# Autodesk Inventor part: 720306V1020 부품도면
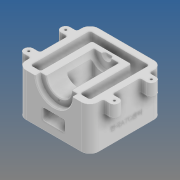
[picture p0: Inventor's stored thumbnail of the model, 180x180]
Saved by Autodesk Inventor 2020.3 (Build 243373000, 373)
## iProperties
Created: 2022-03
Part Number: 720306V1020 부품도면
Material: 일반
Document SubType Name: Modeling
Designer: EZDESIGN
Density: 1 g/cm^3
Appearance: 기본값
Mass: 379.412 g
Surface Area: 845.188 cm^2
Volume: 379.412 cm^3
Author: EZDESIGN
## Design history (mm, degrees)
sketch "스케치1"
  geometry: L1 (55, 55)-(-55, 55); L2 (-55, 55)-(-55, -55); L3 (-55, -55)-(55, -55); L4 (55, -55)-(55, 55); L5 (55, 55)-(-55, -55); L6 (-55, 55)-(55, -55); L7 (45, 45)-(45, -45); L8 (45, -45)-(-45, -45); L9 (-45, -45)-(-45, 45); L10 (-45, 45)-(-30, 45); L11 (-30, 45)-(-30, -33); L12 (-30, -33)-(30, -33); L13 (30, -33)-(30, 45); L14 (30, 45)-(45, 45); 1 further point
  constraints: 28 end point, 7 perpendicular, 2 midpoint, 2 parallel, 2 point on line, 1 horizontal, 1 vertical
  dimensions: "d0" = 110 distance of L3.end L2.end; "d1" = 110 distance of L2.end L1.end; "d2" = 10 distance between parallel lines of L2 L9; "d3" = 25 distance from line of L2 L11.end; "d4" = 60 distance of L11.end L12.end; "d7" = 10 distance between parallel lines of L1 L14; "d8" = 10 distance between parallel lines of L4 L7; "d10" = 10 distance between parallel lines of L8 L3; "d11" = 22 distance between parallel lines of L3 L12
extrude "돌출1" new body sketch "스케치1" distance "d12" = 65; taper "d13" = 0 deg
sketch "스케치2"
  geometry: L1 (55, -55)-(55, 55) reference; L2 (55, 55)-(-55, 55) reference; L3 (-55, 55)-(-55, -55) reference; L4 (-55, -55)-(55, -55) reference; L5 (-45, -45)-(-45, 45) reference; L6 (-45, 45)-(45, 45) reference; L7 (45, 45)-(45, -45) reference; L8 (45, -45)-(30, -45) reference; L9 (30, -45)-(30, 33) reference; L10 (30, 33)-(-30, 33) reference; L11 (-30, 33)-(-30, -45) reference; L12 (-30, -45)-(-45, -45) reference; L13 (-55, 55)-(-55, -55) reference; L14 (55, -55)-(55, 55) reference; L15 (-65, 35)-(-55, 35); L16 (-65, 21)-(-55, 21); L17 (65, 35)-(55, 35); L18 (65, 21)-(55, 21); L19 (-107.819, 0)-(107.819, 0); L20 (-65, -35)-(-55, -35); L21 (-65, -21)-(-55, -21); L22 (65, -21)-(55, -21); L23 (65, -35)-(55, -35); A1 r 7 centre (-65, 28) between (-65, 35) and (-65, 21); A2 r 7 centre (65, 28) between (65, 35) and (65, 21); A3 r 7 centre (-65, -28) between (-65, -35) and (-65, -21); A4 r 7 centre (65, -28) between (65, -35) and (65, -21); 10 further points
  constraints: 18 end point, 10 symmetric about line, 8 point on circle, 5 horizontal, 4 centre point, 4 point on line, 4 tangent, 1 coincident, 1 horizontal alignment, 1 midpoint, 2 other
  dimensions: "d14" = 14 diameter of A1; "d15" = 14 diameter of A2; "d18" = 65 horizontal distance of point (0, 0) A1.centre; "d19" = 130 distance of A2.centre A1.centre; "d20" = 27 distance from line of A1.centre L2; "d21" = 215.63792 distance of L19.start L19.end
extrude "돌출2" join sketch "스케치2" distance "d22" = 20; taper "d23" = 0 deg
sketch "스케치3"
  geometry: L1 (0, 0)-(110, 0) reference; L2 (0, 0)-(0, -65) reference; L3 (110, -65)-(0, -65) reference; L4 (110, 0)-(110, -65) reference; C1 r 28 at (55, 0); 3 further points
  constraints: 1 centre point, 1 coincident
  dimensions: "d24" = 56 diameter of C1
extrude "돌출3" cut sketch "스케치3" distance "d26" = 8; taper "d27" = 0 deg
sketch "스케치4"
  geometry: C1 r 19 at (55, 0); 1 further point
  constraints: 1 centre point, 1 coincident
  dimensions: "d28" = 38 diameter of C1
extrude "돌출4" cut sketch "스케치4" distance "d29" = 72; taper "d30" = 0 deg
sketch "스케치5" dims "d7" = 10
  geometry: L1 (0, 68.674)-(0, -68.674); L2 (0, -21)-(-20, -21) reference; L3 (-20, -21)-(-20, -35) reference; L4 (-20, -35)-(0, -35) reference; L5 (0, -55)-(0, -35) reference; L6 (0, -55)-(-65, -55) reference; L7 (-65, 55)-(-65, -55) reference; L8 (0, 55)-(-65, 55) reference; L9 (0, 35)-(0, 55) reference; L10 (0, 35)-(-20, 35) reference; L11 (-20, 35)-(-20, 21) reference; L12 (-20, 21)-(0, 21) reference; L13 (0, -21)-(0, 21) reference; L14 (0, -33)-(0, 45) reference; L15 (0, -33)-(-65, -33) reference; L16 (-65, 45)-(-65, -33) reference; L17 (0, 45)-(-65, 45) reference; L18 (0, -29)-(-4.613, -29); L19 (-5.479, -28.5)-(-7.5, -25); L20 (-19, -25)-(0, -25) reference; A1 r 1 centre (-4.613, -28) between (-5.479, -28.5) and (-4.613, -29); 2 further points
  constraints: 6 end point, 2 point on circle, 2 point on line, 2 tangent, 1 centre point, 1 coincident, 1 horizontal, 1 midpoint, 1 vertical, 1 vertical alignment
  dimensions: "d31" = 4 distance of L20.end L18.start; "d32" = 15 diameter of L19.end L1; "d33" = 30 deg angle of L1 L19; "d34" = 1 radius of A1; "d35" = 137.34853 distance of L1.start L1.end
revolve "회전1" sketch "스케치5" stored, may be unused: angle "d36" = 90 deg
fillet "모깎기1" dims "d37" = 1
sketch "스케치8"
  geometry: L1 (-35, -33)-(-55.304, 42.776); L2 (-58.202, 45)-(-65, 45); L3 (0, -33)-(-65, -33) reference; L4 (0, -33)-(0, 45) reference; L5 (0, -33)-(-65, -33) reference; L6 (-65, 45)-(-65, -33) reference; L7 (0, 45)-(-65, 45) reference; L8 (0, 55)-(-65, 55) reference; L9 (-65, 55)-(-65, -55) reference; A1 r 3 centre (-58.202, 42) between (-55.304, 42.776) and (-58.202, 45); 3 further points
  constraints: 4 end point, 4 point on line, 2 point on circle, 2 tangent, 1 centre point, 1 horizontal
  dimensions: "d52" = 10 distance between parallel lines of L8 L2; "d53" = 75 deg angle of L3 L1; "d54" = 30 distance from line of L9 L1.start; "d82" = 3 radius of A1 (derived)
extrude "돌출6" cut sketch "스케치8" stored distance "d55" = 60; taper "d56" = 0 deg
sketch "스케치6"
  geometry: L1 (-26.157, 19)-(-9.157, 19); L2 (-9.157, 19)-(-9.157, -19); L3 (-9.157, -19)-(-33.575, -19); L4 (-33.575, -19)-(-53.403, 55); L5 (-26.157, 19)-(-35.803, 55); L6 (-19, 47)-(-19, -24) reference; L7 (0, 35)-(-20, 35) reference; L8 (0, -33)-(0, 45) reference; L9 (0, -33)-(-35, -33) reference; L10 (0, 45)-(-58.202, 45) reference; L11 (0, -21)-(-20, -21) reference; L12 (-20, -21)-(-20, -35) reference; L13 (-20, -35)-(0, -35) reference; L14 (0, -55)-(0, -35) reference; L15 (0, -55)-(-65, -55) reference; L16 (-65, 55)-(-65, -55) reference; L17 (0, 55)-(-65, 55) reference; L18 (0, 35)-(0, 55) reference; L19 (0, 35)-(-20, 35) reference; L20 (-20, 35)-(-20, 21) reference; L21 (-20, 21)-(0, 21) reference; L22 (0, -21)-(0, 21) reference; L23 (-19, 47)-(0, 47) reference; L24 (0, 55)-(0, 55) reference; L25 (0, 47)-(0, 55) reference; L26 (0, 47)-(0, 47) reference; L27 (0, 55)-(0, 47) reference; L28 (-20, -35)-(0, -35) reference; L29 (0, -45)-(-65, -45) reference; L30 (0, 45)-(0, -45) reference; L31 (0, 45)-(-65, 45) reference; L32 (-65, -45)-(-65, 45) reference; L33 (0, -45)-(-65, -45) reference; L34 (-35, -33)-(-55.304, 42.776) reference; L35 (-35, -33)-(-55.9, 45) reference; L36 (0, 45)-(-65, 45) reference; A1 r 3 centre (-58.202, 42) between (-55.304, 42.776) and (-58.202, 45) reference; 1 further point
  constraints: 10 end point, 2 perpendicular, 2 point on line, 1 horizontal, 1 parallel
  dimensions: "d38" = 38 distance of L1.end L2.end; "d42" = 17 distance between parallel lines of L4 L5; "d45" = 36 distance from line of L17 L1.end; "d57" = 5 distance between parallel lines of L34 L4; "d58" = 17 distance of L1.start L1.end
  node "투영된 루프5"
  node "투영된 루프6"
  node "투영된 루프7"
  node "투영된 루프8"
extrude "돌출5" cut sketch "스케치6" stored distance "d47" = 34; taper "d48" = 0 deg
sketch "스케치9" dims "d59" = 46
  geometry: 3 further points
  constraints: 2 vertical alignment, 1 coincident, 2 other
sketch "스케치10" dims "d74" = 46
  geometry: 3 further points
  constraints: 2 vertical alignment, 1 coincident, 2 other
hole "구멍1" sketch "스케치10" at (55, -23) diameter "d60" = 3.242; stored, may be unused: countersink angle "d64" = 82 deg, drill point angle "d66" = 118 deg; dims "d61" = 9, "d62" = 11, "d63" = 2.6, "d65" = 11
sketch "스케치11"
  geometry: L1 (-45, -45)-(-45, 45) reference; L2 (-45, 45)-(45, 45) reference; L3 (45, 45)-(45, -45) reference; L4 (45, -45)-(30, -45) reference; L5 (30, -45)-(30, 33) reference; L6 (30, 33)-(-30, 33) reference; L7 (-30, 33)-(-30, -45) reference; L8 (-30, -45)-(-45, -45) reference; L9 (-7.5, 25)-(-5.479, 28.5) reference; L10 (-4.613, 29)-(4.613, 29) reference; L11 (5.479, 28.5)-(7.5, 25) reference; L12 (7.5, 25)-(18, 25) reference; L13 (19, 24)-(19, -47) reference; L14 (19, -47)-(28, -47) reference; L15 (28, -47)-(28, -55) reference; L16 (28, -55)-(55, -55) reference; L17 (55, -55)-(55, -35) reference; L18 (55, -35)-(65, -35) reference; L19 (65, -21)-(55, -21) reference; L20 (55, -21)-(55, 21) reference; L21 (55, 21)-(65, 21) reference; L22 (65, 35)-(55, 35) reference; L23 (55, 35)-(55, 55) reference; L24 (55, 55)-(-55, 55) reference; L25 (-55, 55)-(-55, 35) reference; L26 (-55, 35)-(-65, 35) reference; L27 (-65, 21)-(-55, 21) reference; L28 (-55, 21)-(-55, -21) reference; L29 (-55, -21)-(-65, -21) reference; L30 (-65, -35)-(-55, -35) reference; L31 (-55, -35)-(-55, -55) reference; L32 (-55, -55)-(-28, -55) reference; L33 (-28, -55)-(-28, -47) reference; L34 (-28, -47)-(-19, -47) reference; L35 (-19, -47)-(-19, 24) reference; L36 (-18, 25)-(-7.5, 25) reference; A1 r 1 centre (-4.613, 28) between (-4.613, 29) and (-5.479, 28.5) reference; A2 r 1 centre (4.613, 28) between (5.479, 28.5) and (4.613, 29) reference; A3 r 1 centre (18, 24) between (19, 24) and (18, 25) reference; A4 r 7 centre (65, -28) between (65, -35) and (65, -21) reference; A5 r 7 centre (65, 28) between (65, 21) and (65, 35) reference; A6 r 7 centre (-65, 28) between (-65, 35) and (-65, 21) reference; A7 r 7 centre (-65, -28) between (-65, -21) and (-65, -35) reference; A8 r 1 centre (-18, 24) between (-18, 25) and (-19, 24) reference; 5 further points
  constraints: 4 coincident
hole "구멍2" sketch "스케치11" at (-65, 28), (-65, -28), (65, -28), (65, 28) diameter "d67" = 3.242; stored, may be unused: countersink angle "d71" = 82 deg, drill point angle "d73" = 118 deg; dims "d68" = 9, "d69" = 11, "d70" = 2.6, "d72" = 11
sketch "스케치12"
  geometry: L1 (110, 0)-(0, 0) reference; L2 (0, 65)-(0, 0) reference; 2 further points
  constraints: 1 other
  dimensions: "d75" = 20 distance from line of L1 point (55, 20); "d76" = 55 distance from line of L2 point (55, 20)
feature "엠보싱1" sketch "스케치12" dims "d0" = 110, "d1" = 110, "d2" = 10, "d3" = 25, "d4" = 60, "d7" = 10, "d8" = 10, "d10" = 10, "d11" = 22, "d77" = 0.5, "d78" = 0
fillet "모깎기2" dims "d79" = 3
fillet "모깎기3" dims "d80" = 3
fillet "모깎기4" dims "d81" = 3
fillet "모깎기5" dims "d83" = 3
fillet "모깎기6" dims "d84" = 3
fillet "모깎기7" dims "d85" = 3
chamfer "모따기1" distance "d86" = 1; stored, may be unused: second distance "d87" = 2, angle "d88" = 45 deg
fillet "모깎기8" dims "d89" = 13
fillet "모깎기10" dims "d91" = 3
fillet "모깎기11" dims "d92" = 3
node "솔리드1"
node "투영된 루프1"
node "투영된 루프2"
node "투영된 루프3" dims "d7" = 10
node "투영된 루프4"
node "투영된 루프11"
node "투영된 루프12"
feature "A9D066F2-1C7D-4E18-AEED-F7BC21143FA4" dims "d60" = 3.242, "d61" = 9, "d62" = 11, "d63" = 2.6, "d64" = 82 deg, "d65" = 11, "d66" = 118 deg
